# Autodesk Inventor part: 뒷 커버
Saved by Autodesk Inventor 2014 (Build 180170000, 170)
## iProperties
Created: 2026-06
Part Number: 뒷 커버
Material: 알루미늄 6061
Document SubType Name: Modeling
Designer: dg
Density: 2.71 g/cm^3
Appearance: 알루미늄 - 평지
Mass: 44.3564 g
Surface Area: 68.2735 cm^2
Volume: 16.3677 cm^3
Author: jhkim
Creation Date: 2026-05-29
Sending System: Autodesk Inventor 2027
Preprocessor: ST-DEVELOPER v20.1
Author: dg
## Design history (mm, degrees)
node "뒷 커버1"
node "솔리드1"
node "기준1"
